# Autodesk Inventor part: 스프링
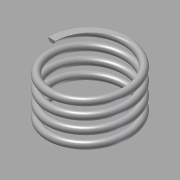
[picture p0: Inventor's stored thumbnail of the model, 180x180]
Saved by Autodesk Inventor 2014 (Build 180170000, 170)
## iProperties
Created: 2015-07
Part Number: 스프링
Material: 강철, 연강
Document SubType Name: Modeling
Designer: Administrator
Mass: 2.70512 g
Surface Area: 9.40935 cm^2
Volume: 0.344162 cm^3
Density: 7.86 g/cm^3
Appearance: 강철
Author: Administrator
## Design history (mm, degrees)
sketch "스케치1"
  geometry: L1 (0, 0)-(8, 0); L2 (8, 0)-(8, 10.5); L3 (8, 10.5)-(0, 10.5); L4 (0, 10.5)-(0, 0); C1 r 0.75 at (8, 0)
  constraints: 8 end point, 2 parallel, 1 centre point, 1 coincident, 1 horizontal, 1 perpendicular
  dimensions: "d0" = 16 diameter of L2 L4; "d1" = 10.5 distance of L1.end L2.end (derived); "d2" = 1.5 diameter of C1
feature "코일1" sketch "스케치1" pitch "d3" = 10; turns "d5" = 4; dims "d4" = 10.5 (= d1), "d6" = 0, angle "d7" = 90 deg, angle "d8" = 90 deg, "d9" = 0, "d10" = 0
node "작업 평면1"
sketch "스케치2"
  geometry: L1 (-0.75, 0)-(0.75, 0) reference; 1 further point
  constraints: 1 horizontal alignment
extrude "돌출1" cut sketch "스케치2" stored distance "d12" = 10; taper "d13" = 0 deg
node "작업 평면2"
sketch "스케치3"
  geometry: L1 (7.25, 0)-(8.75, 0) reference; 1 further point
  constraints: 1 horizontal alignment
extrude "돌출2" cut sketch "스케치3" stored distance "d15" = 10; taper "d16" = 0 deg
node "솔리드1"
node "절단 모서리 투영1"
node "절단 모서리 투영2"
other parameters: "d11" = 90 deg, "d14" = 90 deg
